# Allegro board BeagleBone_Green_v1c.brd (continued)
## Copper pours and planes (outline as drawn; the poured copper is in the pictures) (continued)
DGND on LYR2_GND: 10.16,3.49 12.7,6.03 16.51,6.03 18.1,4.45 18.1,1.91 18.73,1.27 73.98,1.27 75.27,1.51 76.52,1.91 77.15,2.54 77.15,8.26 78.7,9.8 82.96,9.8 84.14,10.99 84.14,20 84.63,20.5 84.63,30.62 84.14,31.11 84.14,44.13 83.5,44.77 77.47,44.77 77.15,45.09 77.15,52.07 76.52,52.7 75.13,53.22 73.66,53.34 18.73,53.34 18.1,52.7 18.1,50.16 16.51,48.58 12.7,48.58 11.11,50.16 11.11,52.39 10.79,52.7 6.35,52.7 3.21,51.4 1.91,48.26 1.91,40.01 2.54,39.37 12.06,39.37 12.7,38.73 12.7,36.83 12.06,36.2 10.48,36.2 9.21,37.47 2.54,37.47 1.91,36.83 1.91,31.43 2.54,30.8 2.54,28.89 1.91,28.26 1.91,22.86 2.54,22.23 9.21,22.23 10.48,23.5 12.06,23.5 12.7,22.86 12.7,20.95 12.06,20.32 2.54,20.32 1.65,19.43 1.65,9.14 1.91,8.89 1.91,5.4 3.81,3.49
DGND on LYR3: 58.32,35.86 66.67,35.86 70.54,32 70.54,19.38 66.6,15.44 55.58,15.44 54.99,16.03 54.99,16.87 55.12,16.99 55.6,16.99 56.21,16.38 56.21,16.28 56.57,15.93 64.77,15.93 66.55,17.7 66.55,30.23 62.15,34.62 58.19,34.62 57.91,34.9 57.91,35.46
DGND on LYR3: 38.23,40.51 40.26,40.51 40.89,39.88 40.89,39.5 40.64,39.24 40.13,39.24 40.01,39.12 40.01,38.1 40.51,37.59 40.51,36.45 40.26,36.2 38.99,36.2 38.61,36.58 38.61,38.23 37.97,38.86 37.97,40.26
DGND on LYR5_PWR: 39.62,4.57 60.58,4.57 61.21,5.21 61.21,15.6 61.39,15.77 70.31,15.77 71.02,16.48 71.02,34.16 69.34,35.84 69.34,40.08 69.37,40.11 71.17,40.11 73.03,38.25 76.78,38.25 77.8,39.27 83.41,39.27 83.9,38.79 83.9,28.52 84.61,27.81 84.61,20.83 84.23,20.45 84.23,11.81 83.34,10.92 79.38,10.92 78.4,9.94 78.4,9.87 77.04,8.51 77.04,2.74 75.56,1.27 26.29,1.27 26.16,1.4 26.16,5.08 26.29,5.21 38.99,5.21
GND_EARTH on TOP, LYR4, LYR5_PWR: 6.35,0.64 2.31,2.31 0.64,6.35 0.64,48.26 2.31,52.3 6.35,53.98 73.66,53.98 82.19,50.44 85.72,41.91 85.72,12.7 82.19,4.17 73.66,0.64 ; 1 cut-out
GND_EARTH on BOTTOM: 6.35,0.64 2.31,2.31 0.64,6.35 0.64,48.26 0.69,49.07 0.86,49.86 0.86,49.99 0.92,50.04 3,52.89 6.35,53.98 73.66,53.98 81.1,51.41 85.37,44.8 85.42,44.75 85.42,44.6 85.65,43.27 85.72,41.91 85.72,12.7 82.19,4.17 73.66,0.64 ; 1 cut-out
GND_EARTH on LYR2_GND, LYR3: 6.35,0.64 2.31,2.31 0.64,6.35 0.64,48.26 2.31,52.3 6.35,53.98 73.66,53.98 82.19,50.44 85.72,41.91 85.72,12.7 82.19,4.17 73.66,0.64 ; 1 cut-out
GND_OSC0 on BOTTOM: 44.07,44.58 52.32,44.58 52.96,45.21 56.52,45.21 56.9,44.83 56.9,38.48 56.52,38.1 53.09,38.1 51.82,39.37 51.44,39.37 50.29,38.23 42.8,38.23 42.67,38.35 42.67,43.18 ; 1 cut-out
GND_OSC1 on TOP: 48.26,10.16 48.51,9.91 53.72,9.91 53.98,10.16 53.98,17.78 53.09,18.67 52.32,18.67 51.05,19.94 51.05,21.84 50.16,22.73 48.9,22.73 48.77,22.61 48.77,20.19 48.13,19.56 48.13,18.67 48.26,18.54
VBUS on BOTTOM: 6.99,16.56 8.79,16.56 9.25,17.02 10.72,17.02 11.33,16.41 11.33,14.5 11.02,14.2 6.99,14.2 6.6,14.58 6.6,16.18
VDD_1V8 on LYR3: 40.28,32.26 33.02,32.26 32.77,32.51 32.77,34.29 33.02,34.54 40.01,34.54 40.41,34.14 40.41,32.38
VDD_1V8 on LYR4: 45.72,25.15 45.47,24.89 41.66,24.89 41.4,25.15 41.4,28.45 41.15,28.7 40.01,28.7 39.75,28.96 39.75,34.29 40.01,34.54 42.55,34.54 42.8,34.8 42.8,35.26 43.18,35.64 45.14,35.64 45.72,35.05 45.72,29.72 45.34,29.34 45.34,29.08 45.72,28.7
VDD_1V8 on LYR5_PWR: 32.51,34.29 32.26,34.04 32.26,28.19 29.59,25.53 29.59,25.27 27.69,23.37 27.69,21.84 26.42,20.57 26.42,17.53 26.67,17.27 30.73,17.27 30.99,17.53 30.99,20.57 33.78,23.37 33.78,34.04 33.53,34.29
VDD_1V8 on LYR5_PWR: 44.7,13.97 44.7,25.27 44.83,25.4 46.74,25.4 46.86,25.27 46.86,20.45 47.24,20.07 48.9,20.07 49.15,19.81 49.15,13.97 48.9,13.72 44.96,13.72
VDD_3V3A on BOTTOM: 42.29,36.45 42.29,35.81 41.91,35.43 41.91,33.27 42.16,33.02 43.31,33.02 43.43,33.15 43.43,33.27 43.05,33.66 43.05,35.56 42.76,35.85 42.76,36.45
VDD_3V3A on BOTTOM: 39.88,29.72 40.39,29.72 40.77,29.34 40.77,29.08 41.02,28.83 41.66,28.83 41.91,28.57 41.91,27.56 41.4,27.56 41.4,27.94 41.02,28.32 40.51,28.32 40.26,28.57 38.61,28.57 38.61,29.08 39.24,29.08
VDD_3V3A on BOTTOM: 48.13,33.02 50.04,33.02 50.29,33.27 50.29,35.18 50.76,35.64 50.76,36.45 50.29,36.45 50.29,35.81 49.91,35.43 49.91,33.91 49.53,33.91 49.53,35.43 49.15,35.81 49.15,36.45 48.69,36.45 48.69,35.86 48.26,35.43 48.26,33.66 48.01,33.4 48.01,33.15
VDD_3V3A on LYR5_PWR: 21.59,11.68 21.34,11.94 21.34,23.37 21.59,23.62 27.18,23.62 27.43,23.37 27.43,22.1 26.16,20.83 26.16,17.4 26.54,17.02 30.86,17.02 31.24,17.4 31.24,20.45 34.04,23.24 34.04,34.04 33.27,34.8 32.51,34.8 32.26,35.05 32.26,37.08 37.85,42.67 37.85,45.97 38.1,46.23 41.27,46.23 41.53,45.97 41.53,44.96 41.78,44.7 49.53,44.7 52.2,47.37 68.66,47.37 69.22,46.81 69.22,43.56 68.55,42.9 68.55,36.17 67.61,35.23 54.25,35.23 53.85,34.82 53.85,34.8 53.59,34.54 50.55,34.54 50.16,34.16 50.16,31.5 49.15,30.48 49.15,29.46 48.9,29.21 42.55,29.21 42.04,28.7 42.04,28.32 41.91,28.19 40.64,28.19 40.39,27.94 40.39,27.3 40.64,27.05 41.91,27.05 42.16,26.8 42.16,26.54 41.15,25.53 41.15,24.89 41.4,24.64 42.8,24.64 43.05,24.89 43.05,25.27 43.18,25.4 44.32,25.4 44.45,25.27 44.45,13.84 44.83,13.46 48.9,13.46 49.15,13.21 49.15,5.59 48.9,5.33 39.88,5.33 39.62,5.59 39.62,11.3 39.24,11.68
VDD_3V3B on TOP: 81.66,42.01 82.14,41.53 83.57,41.53 83.82,41.78 84.02,41.78 84.23,41.58 84.23,40.87 83.52,40.16 76.99,40.16 75.9,39.07 74.75,39.07 74.42,39.4 74.42,40.97 74.75,41.3 77.88,41.3 78.59,42.01
VDD_3V3B on BOTTOM: 25.08,35.24 24.13,35.24 24.13,35.92 23.9,36.14 23.9,38 24.18,38.28 25.58,38.28 26.35,37.5 26.35,33.53 25.75,33.53 25.08,34.2
VDD_3V3B on LYR5_PWR: 18.73,1.27 18.1,1.91 18.1,4.45 16.51,6.03 12.7,6.03 10.16,3.49 3.81,3.49 1.91,5.4 1.91,19.68 2.54,20.32 12.06,20.32 12.7,20.95 12.7,22.99 12.95,23.24 17.78,23.24 21.46,26.92 23.24,26.92 23.62,27.3 23.62,36.96 23.24,37.34 12.95,37.34 12.7,37.59 12.7,38.73 12.06,39.37 2.54,39.37 1.91,40.01 1.91,48.26 3.21,51.4 6.35,52.7 10.79,52.7 11.11,52.39 11.11,50.16 12.7,48.58 16.51,48.58 18.1,50.16 18.1,52.7 18.73,53.34 74.61,53.34 76.52,52.7 77.15,52.07 77.15,45.09 77.47,44.77 82.55,44.77 83.34,43.98 83.34,39.8 83.03,39.5 77.34,39.5 76.43,38.58 73.58,38.58 71.68,40.49 69.7,40.49 69.04,41.15 69.04,42.19 69.57,42.72 69.57,47.04 68.99,47.62 52.07,47.62 49.4,44.96 42.04,44.96 41.78,45.21 41.78,46.23 41.53,46.48 37.85,46.48 37.59,46.23 37.59,42.8 32,37.21 32,28.45 27.43,23.88 21.46,23.88 21.08,23.5 21.08,11.81 21.46,11.43 39.05,11.43 39.37,11.11 39.37,5.71 39.05,5.4 26.04,5.4 25.72,5.08 25.72,1.59 25.4,1.27
VDD_5V on TOP: 19.26,13.74 19.26,13.94 17.8,13.94 17.25,13.39 17.25,12.29 17.4,12.14 18.26,12.14 18.36,12.24 18.36,12.99 19.11,13.74
VDD_5V on BOTTOM: 16.66,13.64 17.73,13.64 17.93,13.44 18.77,13.44 19,13.21 19,12.14 18.41,11.56 16.76,11.56 16.51,11.81 16.51,12.29 16.54,12.32 16.54,13.51
VDD_5V on LYR4: 18.31,13.34 18.69,12.95 18.69,8.81 19.29,8.22 21.5,8.22 23.04,6.68 24.56,6.68 26.31,4.93 26.31,1.7 25.68,1.07 24.21,1.07 23.19,2.08 23.19,2.11 22.76,2.11 21.74,3.12 19.13,3.12 15.6,6.65 15.57,6.65 15.57,12.75 16.15,13.34
VDD_CORE on TOP: 27.3,14.1 27.3,12.95 27.56,12.7 30.63,12.7 31.5,13.56 31.5,14.73 31.38,14.85 26.6,14.85 26.49,14.74 25.91,14.74 25.91,14.54 26.86,14.54
VDD_CORE on BOTTOM: 34.52,30.12 34.98,30.12 35.89,29.21 35.89,24.77 35.74,24.61 35.43,24.61 35.28,24.46 35.28,23.88 35.15,23.75 34.54,23.75 34.39,23.9 34.39,30
VDD_CORE on LYR3: 49.15,25.53 45.97,25.53 45.72,25.78 45.72,26.92 45.34,27.3 42.42,27.3 42.16,27.05 42.16,24.13 41.91,23.88 32.77,23.88 32,24.64 32,25.65 32.51,26.16 33.27,26.16 33.53,26.42 33.53,27.43 33.78,27.69 40.26,27.69 40.26,29.21 41.15,29.21 41.15,30.23 40.51,30.23 40.01,30.73 40.01,31.11 40.39,31.5 41.4,31.5 41.78,31.88 43.43,31.88 45.21,33.66 49.15,33.66 49.4,33.4 49.4,25.78
VDD_MPU on TOP: 25.21,11.75 25.02,11.75 25.02,12.38 25.72,12.38 26.54,11.56 28.83,11.56 29.46,10.92 29.46,8.13 29.08,7.75 27.94,7.75 27.69,8 27.69,9.14 27.18,9.65 26.34,9.65 25.91,10.08 25.91,11.05
VDD_MPU on TOP: 35.33,22.61 36.3,22.61 36.53,22.38 36.53,21.44 36.2,21.11 35.28,21.11 35.05,21.34 35.05,22.33
VDD_MPU on BOTTOM: 26.09,10.31 27.2,10.31 27.46,10.06 27.46,7.85 27.25,7.65 26.19,7.65 25.96,7.87 25.96,10.19
VDD_MPU on LYR3: 45.47,21.08 45.47,26.8 45.21,27.05 42.55,27.05 42.42,26.92 42.42,23.62 41.27,22.48 35.94,22.48 35.81,22.35 35.81,21.34 35.94,21.21 40.13,21.21 40.51,20.83 45.21,20.83
VDD_PHYA on BOTTOM: 21.56,38 23.29,38 23.44,37.85 23.44,35.84 23.14,35.53 23.14,34.14 23.39,33.88 23.39,27.97 23.06,27.64 22.35,27.64 21.95,28.04 21.95,31.98 21.11,32.82 21.11,37.54
VDD_PHYA on LYR5_PWR: 10.54,23.5 9.27,22.23 2.54,22.23 1.91,22.86 1.91,28.26 2.54,28.89 2.54,30.8 1.91,31.43 1.91,36.83 2.54,37.47 9.27,37.47 10.54,36.2 12.06,36.2 12.95,37.08 23.11,37.08 23.37,36.83 23.37,27.43 23.11,27.18 21.34,27.18 17.65,23.5
VDD_PLL on BOTTOM: 48.51,20.07 48.51,22.73 48.77,22.99 48.77,25.15 48.51,25.4 47.75,25.4 47.5,25.15 47.5,21.21 48.01,20.7 48.01,20.07
VDD_PLL on BOTTOM: 38.48,28.07 39.12,28.07 39.24,28.19 40.77,28.19 41.02,27.94 41.02,27.3 40.77,27.05 39.62,27.05 39.12,27.56 38.48,27.56
VDD_PLL on BOTTOM: 43.56,33.53 44.07,33.02 44.2,33.02 45.09,33.91 45.09,34.16 44.7,34.54 44.7,35.43 43.97,36.16 43.97,36.45 43.47,36.45 43.47,35.78 43.56,35.69
VDD_PLL on LYR4: 39.75,28.19 40.89,28.19 41.15,27.94 41.15,27.3 40.89,27.05 38.61,27.05 38.35,27.3 38.35,31.62 38.48,31.75 39.37,31.75 39.5,31.62 39.5,28.45
VDD_PLL on LYR5_PWR: 40.64,27.43 40.77,27.3 42.42,27.3 42.67,27.56 46.35,27.56 47.12,26.8 47.12,25.15 47.24,25.02 48.9,25.02 49.15,25.27 49.15,28.7 48.9,28.96 42.67,28.96 42.29,28.57 42.29,28.19 42.04,27.94 40.77,27.94 40.64,27.81
VDDS on BOTTOM: 47.88,35.49 48.26,35.88 48.26,36.58 48.13,36.7 46.61,36.7 46.35,36.45 46.35,35.56 46.48,35.56 46.74,35.31 46.74,33.91 46.35,33.53 46.35,33.15 46.48,33.02 47.24,33.02 47.88,33.66
VDDS on BOTTOM: 38.61,22.61 39.37,22.61 39.62,22.86 39.62,23.62 39.88,23.88 41.27,23.88 41.53,24.13 41.53,24.51 41.66,24.64 41.91,24.64 42.04,24.77 42.04,25.4 41.91,25.53 41.27,25.53 40.51,26.29 39.62,26.29 39.37,26.04 39.37,25.27 39.12,25.02 38.48,25.02 38.48,22.73
VDDS on LYR4: 46.23,25.65 45.97,25.91 45.97,28.83 45.72,29.08 45.72,29.34 45.97,29.59 45.97,34.54 46.23,34.8 49.15,34.8 49.4,34.54 49.4,24.26 49.15,24 48.01,24 47.75,24.26 47.75,25.4 47.5,25.65
VDDS on LYR5_PWR: 42.67,24.89 41.53,24.89 41.4,25.02 41.4,25.4 42.42,26.42 42.42,26.92 42.8,27.3 46.23,27.3 46.86,26.67 46.86,25.78 46.74,25.65 43.05,25.65 42.8,25.4 42.8,25.02
VDDS_DDR on BOTTOM: 18.47,8.48 19.13,8.48 19.28,8.33 19.28,7.57 19.48,7.37 20.07,7.37 20.73,6.71 21.92,6.71 22.15,6.93 22.15,7.26 22.3,7.42 23.55,7.42 23.72,7.24 23.72,6.12 23.29,5.69 19.15,5.69 18.31,6.53 18.31,8.33
VDDS_DDR on LYR3: 60.33,2.86 60.01,2.54 18.67,2.54 18.41,2.79 18.41,8.38 18.67,8.64 27.18,8.64 28.47,7.34 59.74,7.34 60.33,6.76
VDDS_DDR on LYR5_PWR: 49.4,30.35 49.4,25.27 49.66,25.02 50.04,25.02 50.29,24.77 50.29,20.7 49.4,19.81 49.4,5.84 49.85,5.4 60.33,5.4 60.64,5.71 60.64,15.88 60.96,16.19 70.17,16.19 70.48,16.51 70.48,33.97 70.17,34.29 70.1,34.29 69.47,34.92 54.36,34.92 53.72,34.29 50.67,34.29 50.42,34.04 50.42,31.37
P_L1 on TOP: 23.18,11.06 23.18,10.74 22.61,10.16 22.23,10.16 22.1,10.03 22.1,9.78 22.35,9.53 23.5,9.53 23.75,9.78 23.75,11.11 23.5,11.37
P_L1 on BOTTOM: 21.89,10.31 23.11,10.31 23.39,10.03 23.39,7.8 23.24,7.65 22.02,7.65 21.77,7.9 21.77,10.19
P_L2 on TOP: 24.64,9.53 24.38,9.78 24.38,10.67 24.51,10.79 24.51,11.46 24.64,11.59 24.73,11.59 25.53,10.79 25.53,9.78 25.27,9.53
P_L2 on BOTTOM: 24.05,10.36 25.32,10.36 25.48,10.21 25.48,8 25.12,7.65 23.98,7.65 23.75,7.87 23.75,10.06
P_L3 on TOP: 26.44,15.34 25.91,15.34 25.91,15.56 26.73,15.56 27.3,16.13 27.3,17.53 27.56,17.78 29.34,17.78 29.46,17.65 29.46,17.14 29.34,17.02 28.19,17.02 28.07,16.89 28.07,15.75 27.56,15.24 26.54,15.24
SYS_5V on TOP: 14.1,15.37 15.6,15.37 16,15.77 17.14,15.77 17.35,15.57 17.35,15.39 16.65,14.69 16.65,14.67 16.05,14.07 16.05,12.52 15.85,12.32 14,12.32 13.72,12.04 13.72,7.87 13.02,7.18 12.76,7.18 12.32,6.73 9.53,6.73 9.02,7.24 5.84,7.24 5.59,7.49 5.59,8.51 6.35,9.27 8.13,9.27 9.14,10.29 10.79,10.29 11.3,10.79 11.3,13.72 12.45,14.86 13.59,14.86
SYS_5V on BOTTOM: 3.56,9.53 4.32,9.53 4.45,9.4 4.45,7.75 4.57,7.62 5.46,7.62 5.84,8 5.84,8.89 6.1,9.14 7.11,9.14 7.24,9.02 7.24,7.24 5.84,5.84 4.19,5.84 3.43,6.6 3.43,9.4
SYS_5V on LYR3: 25.02,19.56 26.42,18.16 26.42,17.78 27.43,16.76 27.43,15.24 24.77,12.57 24.77,10.92 24.64,10.79 23.88,10.79 23.11,11.56 21.72,11.56 18.67,14.61 18.41,14.61 17.48,13.67 17.07,13.67 16.21,12.8 13.11,12.8 12.88,13.03 12.88,13.64 13.56,14.33 15.47,14.33 17.02,15.88 17.02,17.14 17.78,17.91 21.46,17.91 22.48,18.92 22.48,19.05 22.99,19.56
USB1_PWR on BOTTOM: 3.33,15.65 4.7,15.65 5.03,15.32 5.46,15.32 5.54,15.24 6.1,15.24 6.35,14.99 6.35,14.2 6.73,13.82 8.08,13.82 8.56,13.34 8.56,12.57 8.05,12.06 5.84,12.06 5.41,12.5 3.56,12.5 3.48,12.57 3.48,14.48 3.2,14.76 3.2,15.52
USB_DC on TOP: 19.43,13.16 20.12,13.16 20.19,13.08 20.19,12.83 20.32,12.7 20.32,10.92 19.94,10.54 19.89,10.54 19.63,10.29 19.63,9.5 20.04,9.09 20.04,7.98 19.86,7.8 18.59,7.8 18.39,8 18.39,11.43 18.97,12.01 18.97,12.7
USB_DC on BOTTOM: 3.96,43.05 6.83,43.05 7.42,42.47 11.2,42.47 11.79,43.05 14.66,43.05 14.96,42.75 14.96,41.99 14.86,41.88 14.15,41.88 13.97,41.71 13.97,41.4 13.72,41.15 13.21,41.15 12.7,40.64 6.48,40.64 5.59,41.53 5.59,41.61 4.78,42.42 4.78,42.47 4.72,42.47 4.57,42.62 3.99,42.62 3.89,42.72 3.89,42.98
USB_DC on BOTTOM: 19.05,10.54 18.8,10.79 18.8,11.56 19.43,12.19 19.43,13.21 19.56,13.34 20.57,13.34 20.95,12.95 20.95,11.56 20.83,11.43 20.83,10.92 20.45,10.54
USB_DC on LYR4: 19.08,10.39 20.19,10.39 20.57,10.77 20.57,11.05 20.95,11.43 20.95,18.03 20.32,18.67 20.32,34.29 19.05,35.56 19.05,38.61 14.73,42.93 10.41,42.93 9.91,42.42 9.91,40.26 10.41,39.75 12.83,39.75 13.46,39.12 13.46,37.72 17.02,34.16 17.02,15.24 18.92,13.34 18.92,12.7 18.95,12.7 18.95,10.52
VDCDC1 on TOP: 20.51,10.73 22.23,10.73 22.96,11.47 22.96,12.19 23.16,12.19 23.16,11.29 22.99,11.11 22.99,10.79 22.48,10.29 21.84,10.29 21.59,10.03 21.59,9.78 21.34,9.53 20.07,9.53 19.81,9.78 19.81,10.16 20.32,10.67 20.45,10.67
VDCDC1 on BOTTOM: 21.21,10.01 21.21,7.92 20.98,7.7 19.94,7.7 19.76,7.87 19.76,8.41 19.35,8.81 18.59,8.81 18.41,8.99 18.41,9.75 18.95,10.29 20.93,10.29
VRTC on LYR3: 48.51,24.64 47.75,24.64 47.5,24.38 47.5,21.59 47.12,21.21 47.12,20.83 47.24,20.7 49.28,20.7 49.4,20.83 49.4,21.21 48.77,21.84 48.77,24.38
VRTC on LYR5_PWR: 47.37,20.32 49.53,20.32 50.04,20.83 50.04,24.64 49.91,24.77 47.24,24.77 47.12,24.64 47.12,20.57

Small or netless copper shapes (teardrops, artwork), in the pictures only: 273 on TOP, 170 on BOTTOM, 85 on LYR3, 34 on LYR4

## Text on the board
BOTTOM: LAYER 6 | SOLDER
Board Geometry/Soldermask Bottom: SMS
Ref Des/Silkscreen Bottom: microSD Card | USB | S/N | BSLK
TOP: BeagleBone_Green | C | v1 | LAYER 1 | COMPONENT
Board Geometry/Soldermask Top: SMC
Ref Des/Silkscreen Top: PWR | USER | RESET | POWER | AM335x | TXD | 3V3 | SDA | GND | RXD | SCL | USB Host | 10/100 Ethernet | (OZ) | LAYER 1 - PRIMARY SIDE - SIGNAL | LAYER 2 - GROUND PLANE | LAYER 3 - SIGNAL | LAYER 4 - SIGNAL | LAYER 5 - SPLIT POWER PLANE | LAYER 6 - SECONDARY SIDE - SIGNAL | LAYER# | COPPER WEIGHT | HALF+PLATING | IMPEDANCE CONTROL | +/- 10% | 50ohm SINGLE ENDED | TRACE WIDTH | TRACE WIDTH / SPACE | 90ohm DIFFERENTIAL | 100ohm DIFFERENTIAL | TSLK | 1 | 5.25 | 4.75 | 4.5/6.5 | 5.0/7.0 | 3.75/7.25 | 4.00/8.00 | LAYER STACK-UP - ALL DIMENSIONS IN INCHES
LYR2_GND: LAYER 2 | GROUND
LYR3: LAYER 3 | SIGNAL
LYR4: LAYER 4 | SIGNAL
LYR5_PWR: LAYER 5 | POWER
DIM_PLACEMENT: V_CUT
DISPLAY_TOP: SPC
DISPLAY_BOTTOM: SPS
DIMENSION: R.250 2X
USER_PART_NUM_TOP: TSLKC
USER_PART_NUM_BOTTOM: BSLKC
User.14: NONE
User.27: FIGURE | FINISHED_SIZE | 8.0 | 12.0 | 35.0 | 36.0 | 40.0 | 63.0 | 92.0 | 125.0 | 24.0 | 80.0 | 128.0 | DRILL CHART: TOP to BOTTOM | ALL UNITS ARE IN MILS | TOLERANCE_DRILL | +3.0/-3.0 | +0.0/-0.0 | +5.0/-5.0 | PLATED | NON-PLATED | QTY | 820 | 28 | 95 | 2 | 4 | 20 | 985 | TOTAL HOLES:
User.28: FIGURE | FINISHED_SIZE | 42.0x20.0 | SLOT HOLES: TOP to BOTTOM | ALL UNITS ARE IN MILS | TOLERANCE_DRILL | +0.0/-0.0 | PLATED | QTY | 2 | TOTAL HOLES:
